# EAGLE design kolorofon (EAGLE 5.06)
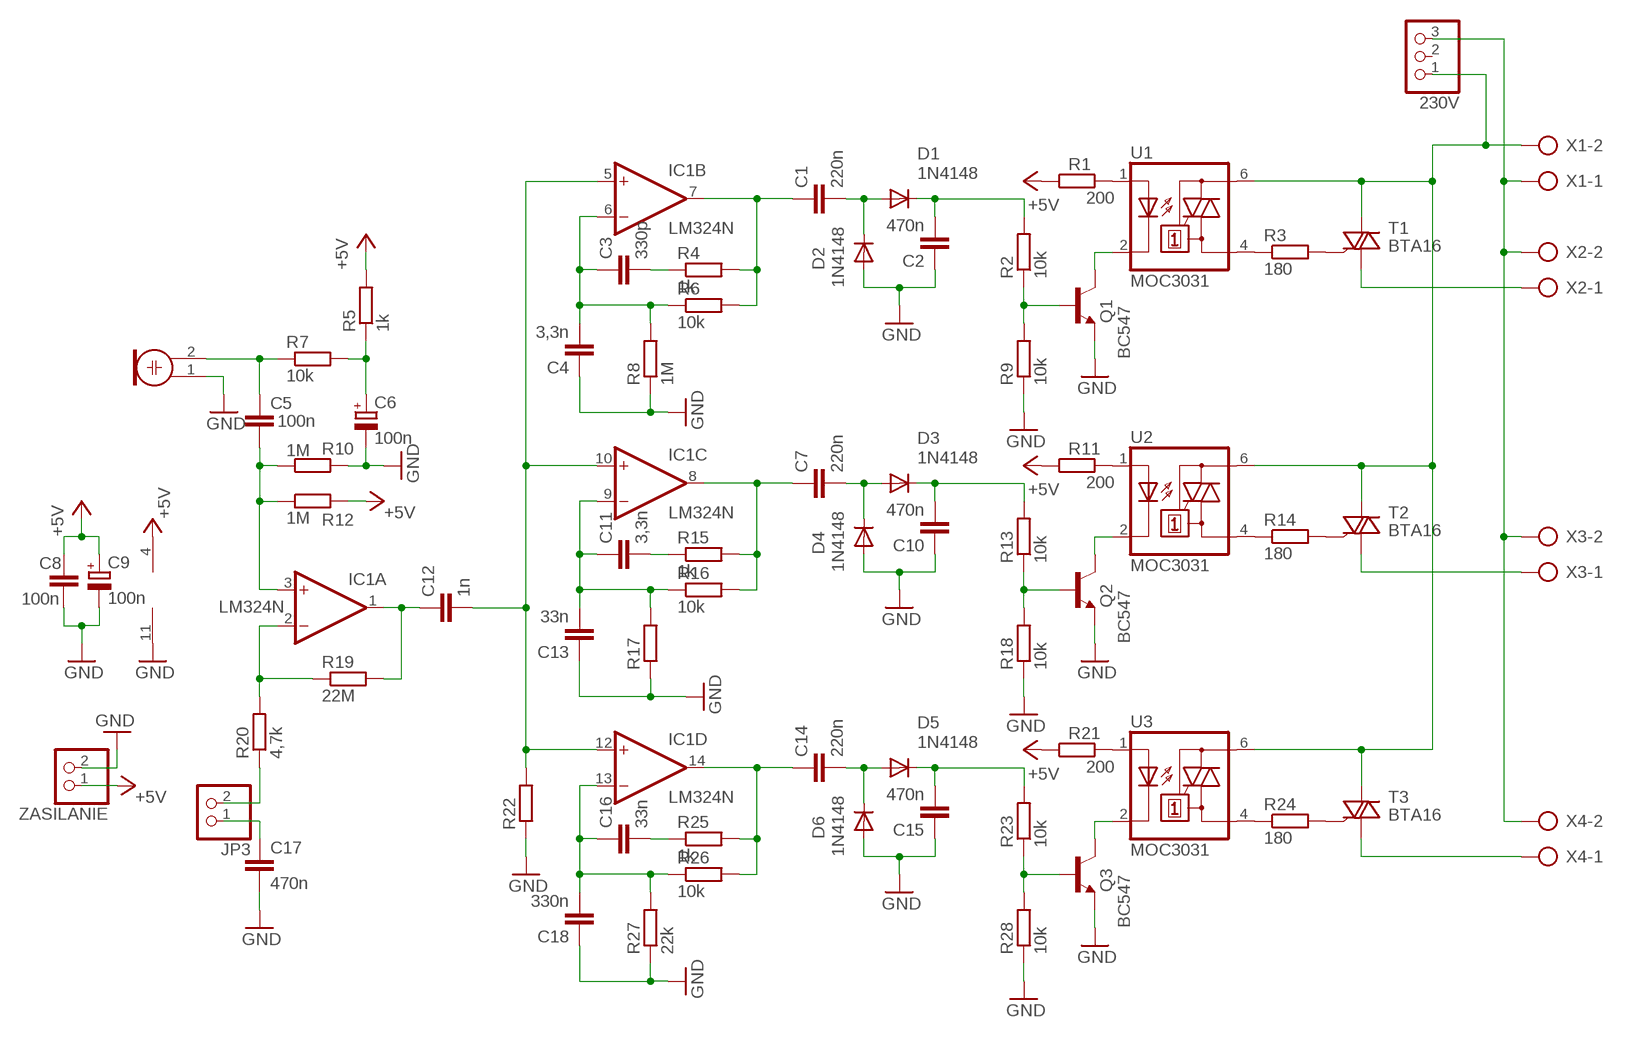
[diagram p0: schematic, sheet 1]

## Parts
230V  PINHD-1X3  [1X03]
C1  220n  C-EU025-030X050  [C025-030X050]
C2  470n  C-EU025-030X050  [C025-030X050]
C3  330p  C-EU025-030X050  [C025-030X050]
C4  3,3n  C-EU025-030X050  [C025-030X050]
C5  100n  C-EU025-030X050  [C025-030X050]
C6  100n  CPOL-EUE2.5-5  [E2,5-5]
C7  220n  C-EU025-030X050  [C025-030X050]
C8  100n  C-EU025-030X050  [C025-030X050]
C9  100n  CPOL-EUE2.5-5  [E2,5-5]
C10  470n  C-EU025-030X050  [C025-030X050]
C11  3,3n  C-EU025-030X050  [C025-030X050]
C12  1n  C-EU025-030X050  [C025-030X050]
C13  33n  C-EU025-030X050  [C025-030X050]
C14  220n  C-EU025-030X050  [C025-030X050]
C15  470n  C-EU025-030X050  [C025-030X050]
C16  33n  C-EU025-030X050  [C025-030X050]
C17  470n  C-EU025-030X050  [C025-030X050]
C18  330n  C-EU025-030X050  [C025-030X050]
D1  1N4148  1N4148DO35-7  [DO35-7]
D2  1N4148  1N4148DO35-7  [DO35-7]
D3  1N4148  1N4148DO35-7  [DO35-7]
D4  1N4148  1N4148DO35-7  [DO35-7]
D5  1N4148  1N4148DO35-7  [DO35-7]
D6  1N4148  1N4148DO35-7  [DO35-7]
IC1  LM324N  [DIL14]
JP3  PINHD-1X2  [1X02]
MIC  MIC  ELECTRET_MICROPHON-F6050AP  [F6050AP]
Q1  BC547  BC447  [TO92-EBC]
Q2  BC547  BC447  [TO92-EBC]
Q3  BC547  BC447  [TO92-EBC]
R1  200  R-EU_0207/10  [0207/10]
R2  10k  R-EU_0207/10  [0207/10]
R3  180  R-EU_0207/10  [0207/10]
R4  1k  R-EU_0207/10  [0207/10]
R5  1k  R-EU_0207/10  [0207/10]
R6  10k  R-EU_0207/10  [0207/10]
R7  10k  R-EU_0207/10  [0207/10]
R8  1M  R-EU_0207/10  [0207/10]
R9  10k  R-EU_0207/10  [0207/10]
R10  1M  R-EU_0207/10  [0207/10]
R11  200  R-EU_0207/10  [0207/10]
R12  1M  R-EU_0207/10  [0207/10]
R13  10k  R-EU_0207/10  [0207/10]
R14  180  R-EU_0207/10  [0207/10]
R15  1k  R-EU_0207/10  [0207/10]
R16  10k  R-EU_0207/10  [0207/10]
R17  R-EU_0207/10  [0207/10]
R18  10k  R-EU_0207/10  [0207/10]
R19  22M  R-EU_0207/10  [0207/10]
R20  4,7k  R-EU_0207/10  [0207/10]
R21  200  R-EU_0207/10  [0207/10]
R22  R-EU_0207/10  [0207/10]
R23  10k  R-EU_0207/10  [0207/10]
R24  180  R-EU_0207/10  [0207/10]
R25  1k  R-EU_0207/10  [0207/10]
R26  10k  R-EU_0207/10  [0207/10]
R27  22k  R-EU_0207/10  [0207/10]
R28  10k  R-EU_0207/10  [0207/10]
T1  BTA16  BT138-V  [TO220BV]
T2  BTA16  BT138-V  [TO220BV]
T3  BTA16  BT138-V  [TO220BV]
U1  MOC3031  MOC3031M  [DIL06]
U2  MOC3031  MOC3031M  [DIL06]
U3  MOC3031  MOC3031M  [DIL06]
X1  AK500/2  [AK500/2]
X2  AK500/2  [AK500/2]
X3  AK500/2  [AK500/2]
X4  AK500/2  [AK500/2]
ZASILANIE  PINHD-1X2  [1X02]

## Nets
230V: 230V.1 T1.T2(A2) T2.T2(A2) T3.T2(A2) U1.6(A2) U2.6(A2) U3.6(A2) X1.2
+5V: C8.1 C9.+ IC1.4(P:V+) R1.1 R5.2 R11.1 R12.2 R21.1 ZASILANIE.1
GND: C2.1 C4.1 C6.- C8.2 C9.- C10.1 C13.1 C15.1 C17.2 C18.1 D2.A D4.A D6.A IC1.11(P:V-) MIC.1 Q1.E Q2.E Q3.E R8.1 R9.1 R10.2 R17.1 R18.1 R22.1 R27.1 R28.1 ZASILANIE.2
N$1: C5.1 MIC.2 R7.1
N$2: C6.+ R5.1 R7.2
N$3: C5.2 IC1.3(A:+IN) R10.1 R12.1
N$4: IC1.2(A:-IN) R19.1 R20.2
N$5: C17.1 JP3.1
N$6: C12.1 IC1.1(A:OUT) R19.2
N$7: C3.1 C4.2 IC1.6(B:-IN) R6.1 R8.2
N$8: C3.2 R4.1
N$9: C1.1 IC1.7(B:OUT) R4.2 R6.2
N$10: C1.2 D1.A D2.C
N$11: C2.2 D1.C R2.2
N$12: Q1.B R2.1 R9.2
N$13: Q1.C U1.2(C)
N$14: C11.1 C13.2 IC1.9(C:-IN) R16.1 R17.2
N$15: C11.2 R15.1
N$16: T1.T1(A1) X2.1
N$17: R14.2 T2.G
N$19: C7.1 IC1.8(C:OUT) R15.2 R16.2
N$20: C7.2 D3.A D4.C
N$21: C10.2 D3.C R13.2
N$22: Q2.B R13.1 R18.2
N$23: Q2.C U2.2(C)
N$24: T2.T1(A1) X3.1
N$25: R14.1 U2.4(A1)
N$26: JP3.2 R20.1
N$27: C16.1 C18.2 IC1.13(D:-IN) R26.1 R27.2
N$28: C16.2 R25.1
N$29: C14.1 IC1.14(D:OUT) R25.2 R26.2
N$30: C14.2 D5.A D6.C
N$31: C15.2 D5.C R23.2
N$32: Q3.B R23.1 R28.2
N$33: Q3.C U3.2(C)
N$34: T3.T1(A1) X4.1
N$35: R3.1 U1.4(A1)
N$36: R3.2 T1.G
N$37: C12.2 IC1.5(B:+IN) IC1.10(C:+IN) IC1.12(D:+IN) R22.2
N$38: 230V.3 X1.1 X2.2 X3.2 X4.2
N$39: R24.1 U3.4(A1)
N$40: R24.2 T3.G
N$41: R1.2 U1.1(A)
N$42: R11.2 U2.1(A)
N$43: R21.2 U3.1(A)
Unconnected: 230V.2

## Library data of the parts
230V = pinhead:PINHD-1X3: PIN HEADER
C1-C5 C7 C8 C10-C18 = resistor:C-EU: CAPACITOR, European symbol
C6 C9 = resistor:CPOL-EU: POLARIZED CAPACITOR, European symbol
D1-D6 = diode:1N4148: DIODE
IC1 = linear:LM324: OP AMP
JP3 ZASILANIE = pinhead:PINHD-1X2: PIN HEADER
MIC = microphon:ELECTRET_MICROPHON-: Electret Condenser Microphone
Q1-Q3 = transistor-npn:BC447*: NPN Transistor
R1-R28 = resistor:R-EU_: RESISTOR, European symbol
T1-T3 = triac:BT138: TRIAC Source: http://www.semiconductors.philips.com BT138_SERIES_2.pdf
U1-U3 = optocoupler:MOC30*: 6-Pin DIP Zero-Cross Optoisolators Triac Driver Output (250/400 Volt Peak) Source: http://www.fairchildsemi.com/ds/MO/MOC3043-M.pdf
X1-X4 = con-ptr500:AK500/2: CONNECTOR

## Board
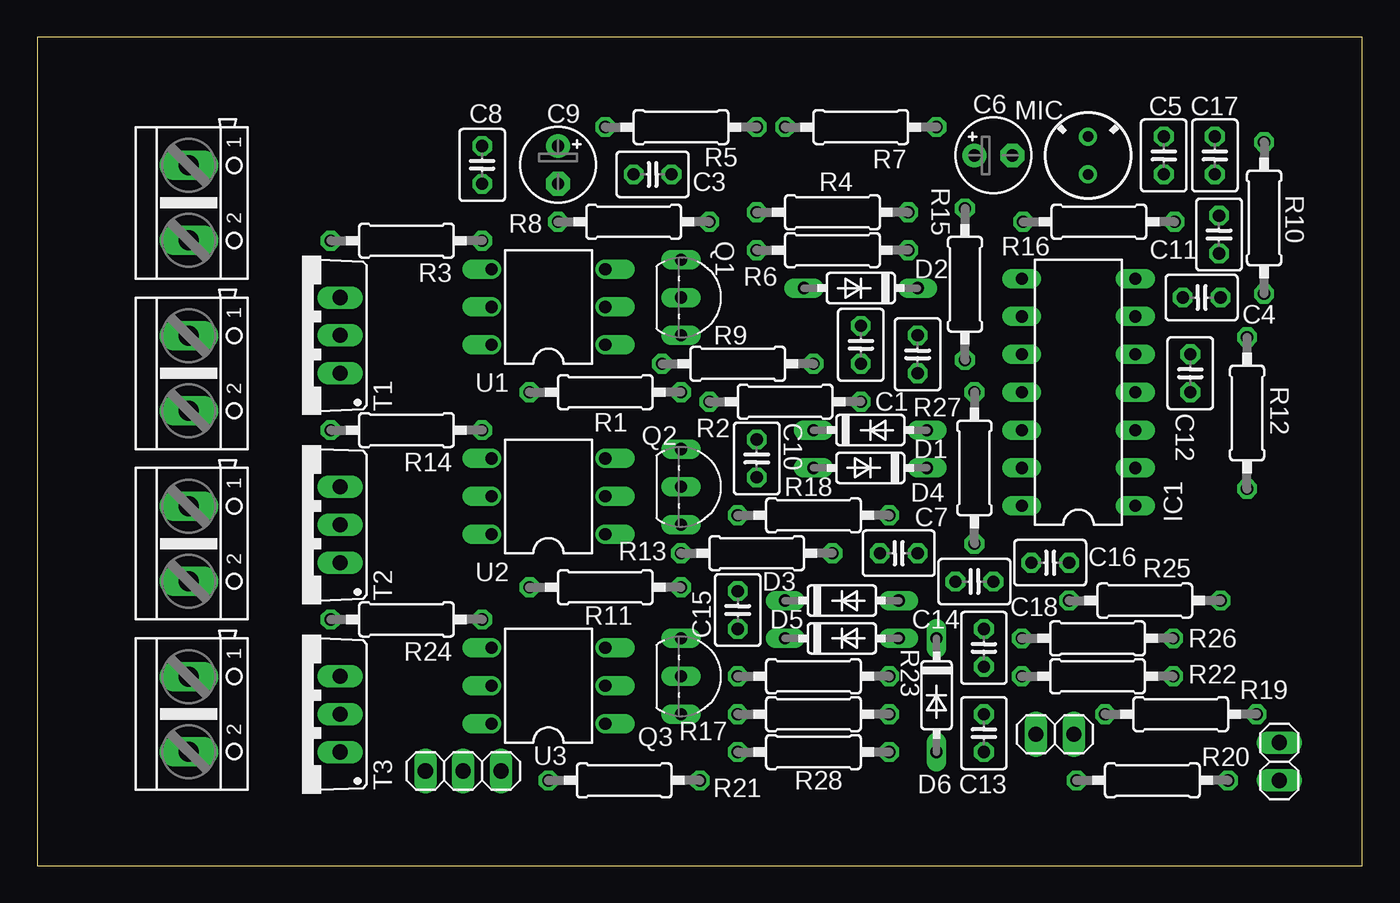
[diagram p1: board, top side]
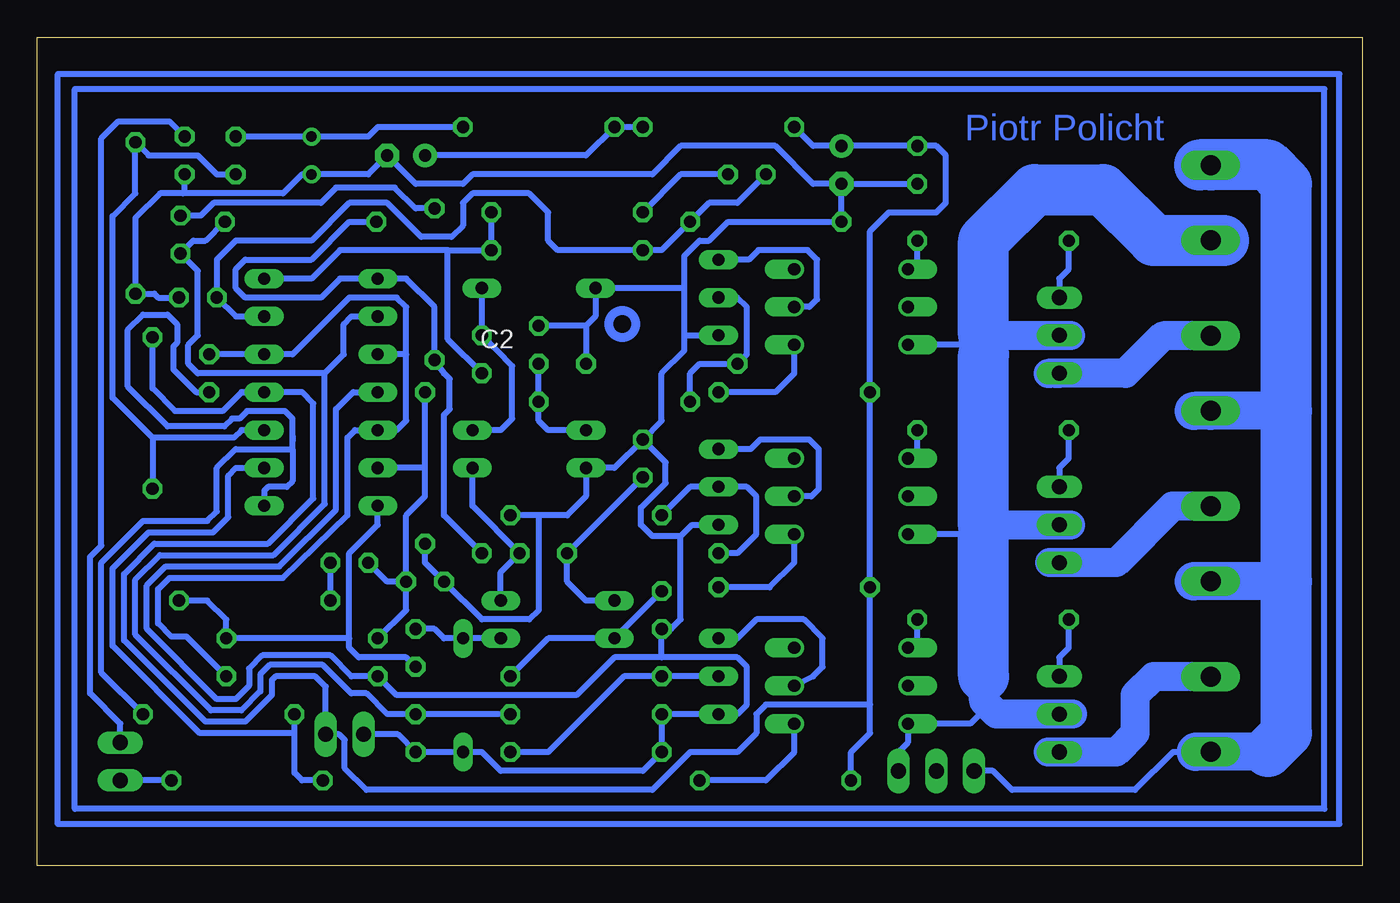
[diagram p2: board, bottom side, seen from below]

Size 88.88 x 55.55 mm. Coordinates in mm from the lower left corner, seen from the top.
Outline: 0,0 88.88,0 88.88,55.55 0,55.55 0,0
Copper layers (1*16): Top 0.035mm / dielectric 1.5mm / Bottom 0.035mm
Design rules "default *": minimum track width 10mil, minimum drill 24mil, track to track 8mil, track to pad 8mil, pad to pad 8mil, via to via 8mil, smd to smd 8mil, copper to edge 40mil, drill to drill 8mil, minimum pad ring 10mil, minimum via ring 8mil, stop-mask expansion 4mil, vias tented up to drill 0mil, thermal gap 10mil

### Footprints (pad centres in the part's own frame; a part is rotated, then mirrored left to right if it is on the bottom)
1X03 = drill 1.016 long: 1 -2.54,0; 2 0,0; 3 2.54,0
C025-030X050 = drill 0.813 octagon: 1 -1.27,0; 2 1.27,0
E2,5-5 = drill 0.813 pad 1.6 round: + -1.27,0 | drill 0.813 pad 1.6 octagon: - 1.27,0
DO35-7 = drill 0.813 long: A 3.81,0; C -3.81,0
DIL14 = drill 0.813 long: 1 -7.62,-3.81; 2 -5.08,-3.81; 3 -2.54,-3.81; 4 0,-3.81; 5 2.54,-3.81; 6 5.08,-3.81; 7 7.62,-3.81; 8 7.62,3.81; 9 5.08,3.81; 10 2.54,3.81; 11 0,3.81; 12 -2.54,3.81; 13 -5.08,3.81; 14 -7.62,3.81
1X02 = drill 1.016 long: 1 -1.27,0; 2 1.27,0
F6050AP = drill 0.7 pad 1.2 round: 1 0,1.27; 2 0,-1.27
TO92-EBC = drill 0.813 long: B 0,-1.27; C -2.54,-1.27; E 2.54,-1.27
0207/10 = drill 0.813 octagon: 1 -5.08,0; 2 5.08,0
TO220BV = drill 1.016 long: G 2.54,-2.54; T1 -2.54,-2.54; T2 0,-2.54
DIL06 = drill 0.813 offset: 1 -2.54,-3.81; 2 0,-3.81; 3 2.54,-3.81; 4 2.54,3.81; 5 0,3.81; 6 -2.54,3.81
AK500/2 = drill 1.321 long: 1 -2.515,0; 2 2.515,0

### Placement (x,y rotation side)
230V  28.57,6.35 180 top
C1  59.05,34.29 90 top
C2  55.24,34.92 270 top
C3  41.27,46.35 0 top
C4  78.11,38.1 180 top
C5  75.56,47.62 270 top
C6  64.14,47.62 0 top
C7  57.78,20.95 180 top
C8  29.84,46.99 270 top
C9  34.92,46.99 270 top
C10  48.26,27.3 270 top
C11  79.28,42.33 90 top
C12  77.34,33.02 90 top
C13  63.5,8.89 90 top
C14  63.5,14.61 90 top
C15  46.99,17.14 90 top
C16  67.94,20.32 0 top
C17  78.99,47.62 270 top
C18  62.87,19.05 0 top
D1  55.88,29.21 0 top
D2  55.24,38.73 180 top
D3  53.98,17.78 0 top
D4  55.88,26.67 180 top
D5  53.98,15.24 0 top
D6  60.33,11.43 270 top
IC1  69.85,31.75 90 top
JP3  83.31,6.99 270 top
MIC  70.48,47.62 180 top
Q1  44.45,38.1 270 top
Q2  44.45,25.4 270 top
Q3  44.45,12.7 270 top
R1  38.1,31.75 0 top
R2  50.16,31.11 0 top
R3  24.77,41.91 180 top
R4  53.34,43.81 0 top
R5  43.18,49.53 180 top
R6  53.34,41.27 0 top
R7  55.24,49.53 180 top
R8  40.01,43.18 0 top
R9  46.99,33.66 180 top
R10  82.3,43.43 270 top
R11  38.1,18.67 0 top
R12  81.15,30.35 90 top
R13  48.26,20.95 0 top
R14  24.77,29.21 180 top
R15  62.23,38.99 270 top
R16  71.22,43.18 180 top
R17  52.07,10.16 0 top
R18  52.07,23.5 180 top
R19  76.71,10.16 0 top
R20  74.8,5.71 180 top
R21  39.37,5.71 0 top
R22  71.12,12.7 0 top
R23  52.07,12.7 0 top
R24  24.77,16.51 180 top
R25  74.3,17.78 0 top
R26  71.12,15.24 0 top
R27  62.87,26.67 90 top
R28  52.07,7.62 0 top
T1  17.78,35.56 90 top
T2  17.78,22.86 90 top
T3  17.78,10.16 90 top
U1  34.29,37.47 90 top
U2  34.29,24.77 90 top
U3  34.29,12.06 90 top
X1  10.16,44.45 270 top
X2  10.16,33.02 270 top
X3  10.16,21.59 270 top
X4  10.16,10.16 270 top
ZASILANIE  68.26,8.81 180 top

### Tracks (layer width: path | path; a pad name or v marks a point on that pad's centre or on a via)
230V
  Bottom 0.406: 230V.1 31.11,7.62 30.48,8.26 U3.6 26.29,9.53 25.08,10.73 | U1.6 26.04,34.92 25.4,34.29 | 25.4,22.23 U2.6
  Bottom 1.93: 25.4,35.56 T1.T2 20.07,35.56 | 25.4,12.7 25.4,11.05 25.08,10.73 24.51,10.16 T3.T2 19.43,10.16 | 24.77,22.86 T2.T2 20.19,22.86 | 20.19,22.86 19.81,22.86 | 20.07,35.56 19.68,35.56 | 20.19,22.86 19.56,22.86 | 20.07,35.56 19.56,35.56
  Bottom 2.184: 24.77,22.86 24.89,22.99 25.15,22.99 25.4,22.73
  Bottom 2.54: 25.4,34.29 25.4,35.56 | 25.4,22.23 25.4,22.73
  Bottom 3.429: 25.4,35.56 25.4,41.91 21.97,45.34 17.4,45.34 13.99,41.94 X1.2 9.3,41.94 | 25.4,12.7 25.4,22.23 | 25.4,22.73 25.4,34.29
+5V
  Bottom 0.406: 33.02,10.79 33.02,8.89 34.29,7.62 R21.1 | 33.02,10.79 R11.1 R1.1 33.02,42.55 31.75,43.81 28.57,43.81 27.94,44.45 27.94,47.62 28.57,48.26 C8.1 C9.+ 36.83,48.26 R5.2 | 33.02,10.79 40.01,10.79 40.64,10.16 40.64,8.89 41.91,7.62 45.09,7.62 47.62,5.08 66.8,5.08 68.25,6.53 68.25,8.43 68.63,8.81 ZASILANIE.1 69.53,12 70.23,12.7 72.9,12.7 73.15,12.45 73.15,11.43 74.93,9.65 77.6,9.65 83.06,15.11 83.06,19.56 81.03,21.59 73.41,21.59 70.36,24.64 70.36,30.99 71.12,31.75 75.18,31.75 | 75.18,31.75 76.45,30.48 79.63,30.48 81.15,32 R12.2 | 75.18,31.75 IC1.4
GND
  Bottom 0.406: 45.72,22.1 47.62,22.1 48.39,22.86 48.39,24 46.74,25.65 46.74,27.05 C10.1 | 45.72,22.1 44.96,22.86 Q2.E | 45.72,22.1 45.72,16.51 46.35,15.88 C15.1 46.99,13.97 | C10.1 46.99,29.84 46.99,33.02 45.47,34.54 45.47,35.56 | C10.1 50.16,26.67 D4.A 52.07,24.77 53.34,23.5 55.24,23.5 | 46.99,13.97 41.91,13.97 41.27,13.34 41.27,10.79 41.91,10.16 Q3.E R17.1 R28.1 48.26,6.35 57.78,6.35 59.05,7.62 D6.A C13.1 64.69,8.81 ZASILANIE.2 | 55.24,23.5 R18.1 | 55.24,23.5 55.24,17.14 55.88,16.51 59.05,16.51 C18.1 62.87,20.32 R27.1 | 45.47,35.56 Q1.E | C9.- C8.2 | C9.- R8.1 42.55,43.18 43.81,41.91 44.45,41.91 45.47,40.89 45.47,38.73 | 45.47,35.56 45.47,38.73 | 45.47,38.73 D2.A 51.44,36.83 52.07,36.2 | 52.07,36.2 R9.1 | 46.99,13.97 50.16,13.97 52.7,11.43 64.77,11.43 R22.1 67.82,12.7 69.22,14.1 73.79,14.1 74.68,13.21 74.68,12.06 75.56,11.18 76.83,11.18 81.53,15.88 81.53,18.8 80.26,20.07 72.64,20.07 68.83,23.88 68.83,30.61 67.69,31.75 IC1.11 | 79.12,45.09 72.39,45.09 71.12,46.35 MIC.1 66.67,46.35 C6.- 63.5,45.72 60.33,45.72 59.69,46.35 47.62,46.35 45.72,48.26 39.37,48.26 36.83,45.72 C9.- | C17.2 78.99,45.21 79.12,45.09 | 79.12,45.09 80.64,45.09 82.3,43.43 R10.2 81.03,38.35 80.77,38.1 C4.1 | 52.07,36.2 C2.1
N$1
  Bottom 0.406: C5.1 MIC.2 66.67,48.9 66.04,49.53 R7.1
N$2
  Bottom 0.406: C6.+ 52.07,47.62 R7.2 R5.1
N$3
  Bottom 0.406: IC1.3 75.18,29.21 75.69,28.7 81.15,28.7 | C5.2 76.83,46.35 78.11,47.62 81.41,47.62 R10.1 82.3,45.09 83.82,43.56 83.82,31.37 81.15,28.7 | 81.15,28.7 R12.1
N$4
  Bottom 0.406: IC1.2 75.56,26.67 76.07,26.16 76.07,23.37 77.09,22.35 81.41,22.35 83.82,19.94 83.82,14.73 77.98,8.89 71.63,8.89 | R20.2 71.12,5.71 71.63,6.22 71.63,8.89 | 71.63,8.89 R19.1
N$5
  Bottom 0.406: C17.1 80.01,49.91 83.44,49.91 84.58,48.77 84.58,21.46 85.34,20.7 85.34,11.56 83.31,9.53 JP3.1
N$6
  Bottom 0.406: C12.1 78.23,31.75 79.76,33.27 79.76,34.8 79.5,35.05 79.5,36.32 80.14,36.96 81.79,36.96 82.8,35.94 82.8,32.13 80.14,29.46 76.33,29.46 75.82,29.97 75.31,29.97 74.8,30.48 72.26,30.48 71.75,29.97 71.75,28.83 | 71.75,28.83 71.75,28.45 | 71.75,27.94 71.75,25.78 72.14,25.4 73.41,25.4 73.66,25.15 IC1.1 | 71.75,27.94 71.75,28.83 | R19.2 84.58,12.95 84.58,20.32 81.79,23.11 77.47,23.11 76.83,23.75 76.83,26.67 75.56,27.94 71.75,27.94
N$7
  Bottom 0.406: C3.1 41.91,44.45 43.81,44.45 R8.2 46.99,41.27 R6.1 53.98,41.27 54.61,41.91 54.61,43.81 55.88,45.09 59.69,45.09 60.33,44.45 60.33,42.93 61.09,42.16 63.12,42.16 65.41,44.45 67.94,44.45 70.48,41.91 75.56,41.91 76.83,40.64 C4.2 75.56,36.83 IC1.6
N$8
  Bottom 0.406: C3.2 45.72,46.35 R4.1
N$9
  Bottom 0.406: IC1.7 70.48,39.37 68.58,41.27 61.34,41.27 | R4.2 R6.2 61.34,41.27 | C1.1 61.34,35.31 61.34,41.27
N$10
  Bottom 0.406: D1.A 57.78,29.21 57.02,29.97 57.02,33.5 C1.2 D2.C
N$11
  Bottom 0.406: D1.C 54.61,29.21 55.24,29.84 R2.2 C2.2
N$12
  Bottom 0.406: R2.1 45.09,33.02 44.45,33.66 R9.2 41.27,34.29 41.27,37.47 41.91,38.1 Q1.B
N$13
  Bottom 0.406: U1.2 37.08,37.47 36.58,37.97 36.58,40.64 37.21,41.27 40.51,41.27 41.15,40.64 Q1.C
N$14
  Bottom 0.406: IC1.9 67.82,36.83 68.33,36.32 68.33,34.29 69.6,33.02 | R17.2 C13.2 65.41,10.16 66.8,11.56 67.82,11.56 69.72,13.46 73.28,13.46 73.91,12.83 73.91,11.68 75.18,10.41 77.22,10.41 82.3,15.49 82.3,19.18 80.64,20.83 73.03,20.83 69.6,24.26 69.6,33.02 | R16.1 76.33,43.18 77.6,41.91 78.42,41.91 C11.1 78.11,39.88 78.11,35.56 78.74,34.92 78.74,33.66 78.11,33.02 69.6,33.02
N$15
  Bottom 0.406: C11.2 77.91,43.59 77.06,44.45 69.85,44.45 68.83,45.47 64.9,45.47 63.5,44.07 R15.1
N$16
  Bottom 1.93: X2.1 13.36,35.53 15.88,33.02 T1.T1 20.57,33.02 | 20.57,33.02 20.95,33.02 | 20.57,33.02 21.08,33.02
N$17
  Bottom 0.406: R14.2 19.68,27.3 20.32,26.67 T2.G
N$19
  Bottom 0.406: C7.1 61.59,23.5 61.59,30.23 61.21,30.61 61.21,32.64 61.59,33.02 R15.2 62.23,37.47 64.14,39.37 IC1.8 68.58,39.37 69.85,38.1 74.93,38.1 75.56,38.73 75.56,40.01 74.93,40.64 70.48,40.64 67.94,43.18 R16.2
N$20
  Bottom 0.406: D3.A 57.78,19.68 C7.2 59.69,24.13 D4.C
N$21
  Bottom 0.406: D3.C 52.07,17.78 53.34,19.05 R13.2 C10.2
N$22
  Bottom 0.406: R18.2 45.09,25.4 Q2.B 41.27,25.4 40.64,24.77 40.64,22.23 41.91,20.95 R13.1
N$23
  Bottom 0.406: U2.2 36.96,24.77 36.45,25.27 36.45,27.94 37.08,28.57 40.39,28.57 41.02,27.94 Q2.C
N$24
  Bottom 1.93: X3.1 12.72,24.11 16.51,20.32 T2.T1 20.95,20.32
N$25
  Bottom 0.406: R14.1 29.84,27.3 U2.4
N$26
  Bottom 0.406: R20.1 JP3.2
N$27
  Bottom 0.406: C18.2 64.14,23.5 62.87,24.77 62.87,26.67 | 62.87,26.67 R27.2 | 62.87,26.67 IC1.13 | C16.1 65.41,19.05 C18.2 | C18.2 64.14,17.14 R26.1
N$28
  Bottom 0.406: R25.1 C16.2
N$29
  Bottom 0.406: IC1.14 66.04,22.86 67.94,20.95 67.94,15.24 | 67.94,15.24 67.94,14.61 67.31,13.97 64.14,13.97 C14.1 | R25.2 77.47,17.78 76.2,16.51 R26.2 67.94,15.24
N$30
  Bottom 0.406: D5.A D6.C 61.59,15.24 62.23,15.88 C14.2
N$31
  Bottom 0.406: C15.2 D5.C 54.61,15.24 R23.2
N$32
  Bottom 0.406: Q3.B R23.1 49.53,12.7 54.61,7.62 R28.2
N$33
  Bottom 0.406: Q3.C 41.91,15.24 40.64,16.51 37.47,16.51 36.2,15.24 36.2,13.34 36.83,12.7 U3.2
N$34
  Bottom 1.93: X4.1 13.99,12.68 15.24,11.43 15.24,8.89 16.51,7.62 T3.T1 21.08,7.62
N$35
  Bottom 0.406: R3.1 29.84,40.01 U1.4
N$36
  Bottom 0.406: R3.2 19.68,40.01 20.32,39.37 T1.G
N$37
  Bottom 0.406: 64.14,34.29 64.14,29.84 64.77,29.21 IC1.12 67.56,29.21 68.07,28.7 68.07,23.5 72.39,19.3 80.01,19.3 80.77,18.54 80.77,16.26 79.88,15.37 78.87,15.37 R22.2 | 64.14,34.29 64.14,37.47 64.77,38.1 67.94,38.1 71.75,34.29 IC1.5 C12.2 | 64.14,34.29 IC1.10
N$38
  Bottom 0.406: 230V.3 24.77,6.35 23.5,5.08 15.24,5.08 12.7,7.62 11.18,7.62 10.19,7.62 X4.2
  Bottom 2.54: 6.33,7.64 X4.2 11.15,7.64 11.18,7.62 | 10.13,46.99 X1.1 | 5.08,30.48 5.11,30.5 X2.2 11.28,30.5 11.3,30.48 | 5.08,19.05 6.35,19.05 6.38,19.07 X3.2 11.28,19.07 11.3,19.05 | 10.92,46.99 11.3,46.99
  Bottom 3.429: 6.33,7.64 5.08,8.89 5.08,19.05 5.08,30.48 5.08,45.72 6.35,46.99 10.13,46.99 10.92,46.99
N$39
  Bottom 0.406: R24.1 29.84,14.61 U3.4
N$40
  Bottom 0.406: R24.2 19.68,14.61 20.32,13.97 T3.G
N$41
  Bottom 0.406: R1.2 39.37,31.75 38.1,33.02 U1.1
N$42
  Bottom 0.406: R11.2 39.75,18.67 38.1,20.32 U2.1
N$43
  Bottom 0.406: R21.2 40.01,5.71 38.1,7.62 U3.1
N$44
  Bottom 0.406: 2.54,3.81 2.54,52.07 86.36,52.07 86.36,3.81 2.54,3.81
N$45
  Bottom 0.406: 1.52,2.79 87.5,2.79 87.5,53.09 1.52,53.09 1.52,2.79
(copper drawn outside any net)
  shapes: Bottom circle x1

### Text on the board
Bottom: Piotr Policht
tDocu: Zasilanie | 1 | Kolorofon | V1.0 | 2 | PR1 | 3 | ZAS. | +5V | GND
